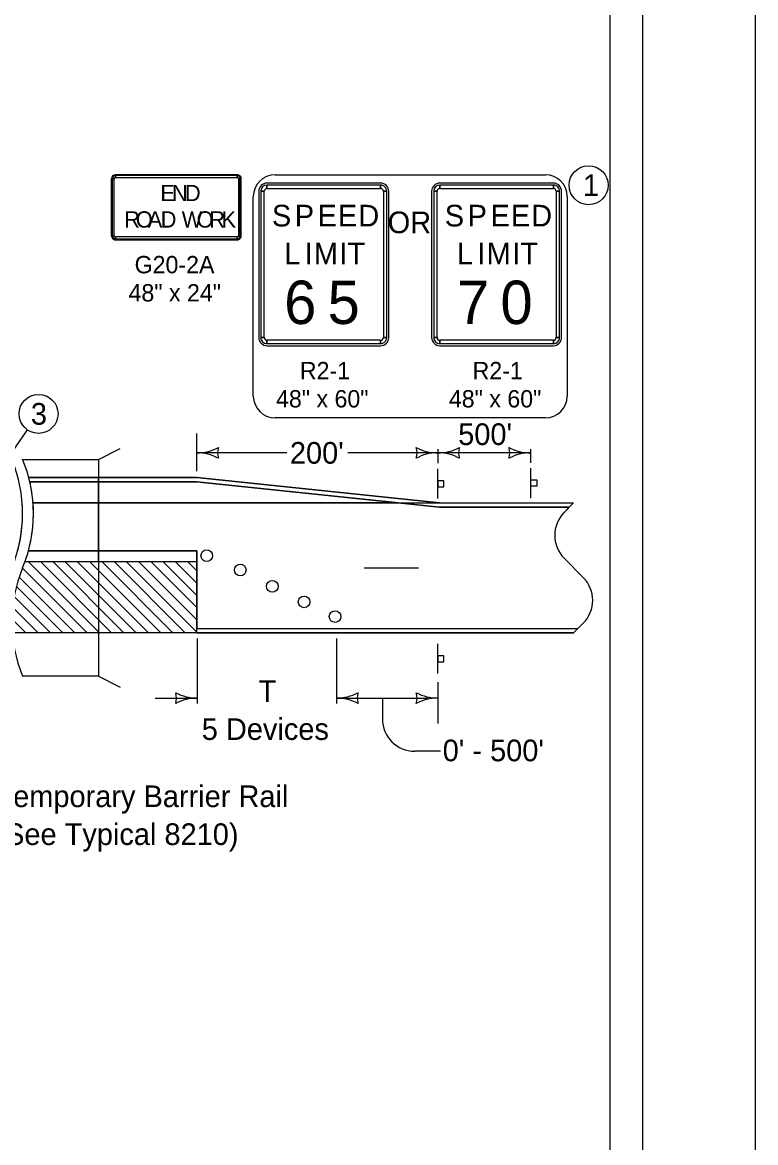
# Model space of a CAD drawing. Extents: x -2135039 to 114557, y -2139150 to -409929.
# Drawn here: x -2128772 to -2128095, y -2138203 to -2137170 of the extents above; entities that cross this region are included whole.
import ezdxf

# ---------------------------------------------------------------- set-up
doc = ezdxf.new("R2010")
doc.units = 0
for name, color, linetype in [('dsnDOTLogo', 7, 'Continuous'), ('dsnNonPlotable', 7, 'Continuous'), ('dsnStdDimension', 7, 'Continuous'), ('dsnStdLabel', 7, 'Continuous'), ('dsnStdLineWork', 7, 'Continuous'), ('dsnStdNote', 7, 'Continuous'), ('dsnStdShading', 7, 'Continuous'), ('Level 1', 7, 'Continuous'), ('StdDimension', 7, 'Continuous')]:
    doc.layers.add(name, color=color, linetype=linetype)

msp = doc.modelspace()

# ---------------------------------------------------------------- linework, layer by layer
at = {"layer": 'dsnDOTLogo'}
msp.add_lwpolyline([(-2131438.9, -2139150.4), (-2128095, -2139150.4), (-2128095, -2136566.4), (-2131438.9, -2136566.4)], close=True, dxfattribs=at)
at = {"layer": 'dsnNonPlotable'}
msp.add_line((-2128229.5, -2137085.9), (-2128229.5, -2138555.9), dxfattribs=at)
at = {"layer": 'dsnStdDimension'}
for p, q in [((-2128388.4, -2137563.5), (-2128388.4, -2137576.4)), ((-2128302.7, -2137566.8), (-2128388.4, -2137566.8)), ((-2128302.7, -2137563.5), (-2128302.7, -2137576.1))]:
    msp.add_line(p, q, dxfattribs=at)
at = {"layer": 'dsnStdLabel'}
for p, q in [((-2128573.6, -2137310.1), (-2128686.1, -2137310.1)), ((-2128686.1, -2137312.6), (-2128686.1, -2137311)), ((-2128573.6, -2137311), (-2128573.6, -2137312.6)), ((-2128689.9, -2137313.9), (-2128689.9, -2137366.4)), ((-2128689, -2137313.9), (-2128687.4, -2137313.9)), ((-2128572.4, -2137313.9), (-2128570.8, -2137313.9)), ((-2128569.9, -2137366.4), (-2128569.9, -2137313.9)), ((-2128441.2, -2137317.9), (-2128546.2, -2137317.9)), ((-2128546.2, -2137322.9), (-2128546.2, -2137319.7)), ((-2128441.2, -2137319.7), (-2128441.2, -2137322.9)), ((-2128281.6, -2137317.9), (-2128386.6, -2137317.9)), ((-2128386.6, -2137322.9), (-2128386.6, -2137319.7)), ((-2128281.6, -2137319.7), (-2128281.6, -2137322.9)), ((-2128553.7, -2137325.4), (-2128553.7, -2137460.4)), ((-2128551.8, -2137325.4), (-2128548.7, -2137325.4)), ((-2128438.7, -2137325.4), (-2128435.6, -2137325.4)), ((-2128433.7, -2137460.4), (-2128433.7, -2137325.4)), ((-2128394.1, -2137325.4), (-2128394.1, -2137460.4)), ((-2128392.2, -2137325.4), (-2128389.1, -2137325.4)), ((-2128279.1, -2137325.4), (-2128276, -2137325.4)), ((-2128274.1, -2137460.4), (-2128274.1, -2137325.4)), ((-2128687.4, -2137366.4), (-2128689, -2137366.4)), ((-2128686.1, -2137369.2), (-2128686.1, -2137367.6)), ((-2128686.1, -2137370.1), (-2128573.6, -2137370.1)), ((-2128573.6, -2137367.6), (-2128573.6, -2137369.2)), ((-2128570.8, -2137366.4), (-2128572.4, -2137366.4)), ((-2128548.7, -2137460.4), (-2128551.8, -2137460.4)), ((-2128546.2, -2137466), (-2128546.2, -2137462.9)), ((-2128441.2, -2137462.9), (-2128441.2, -2137466)), ((-2128435.6, -2137460.4), (-2128438.7, -2137460.4)), ((-2128389.1, -2137460.4), (-2128392.2, -2137460.4)), ((-2128386.6, -2137466), (-2128386.6, -2137462.9)), ((-2128281.6, -2137462.9), (-2128281.6, -2137466)), ((-2128276, -2137460.4), (-2128279.1, -2137460.4)), ((-2128546.2, -2137467.9), (-2128441.2, -2137467.9)), ((-2128386.6, -2137467.9), (-2128281.6, -2137467.9)), ((-2128388.4, -2137609), (-2128388.4, -2137581.5)), ((-2128302.7, -2137581), (-2128302.7, -2137608.5)), ((-2128611, -2137593.4), (-2128386.8, -2137616.9)), ((-2128386.8, -2137616.9), (-2128267, -2137616.9)), ((-2128753.3, -2137657.2), (-2128766.4, -2137657.2)), ((-2128701.8, -2137657.2), (-2128753.3, -2137657.2)), ((-2128611, -2137657.2), (-2128701.8, -2137657.2)), ((-2128701.8, -2137657.2), (-2128701.8, -2137667.2)), ((-2128701.8, -2137667.2), (-2128701.8, -2137657.2)), ((-2128611, -2137667.2), (-2128611, -2137657.2)), ((-2128769.5, -2137667.2), (-2128756.5, -2137667.2)), ((-2128766.6, -2137667.2), (-2128700.9, -2137732.9)), ((-2128756.5, -2137667.2), (-2128701.8, -2137667.2)), ((-2128755.3, -2137667.2), (-2128689.6, -2137732.9)), ((-2128744, -2137667.2), (-2128678.2, -2137732.9)), ((-2128732.7, -2137667.2), (-2128666.9, -2137732.9)), ((-2128721.3, -2137667.2), (-2128655.6, -2137732.9)), ((-2128710, -2137667.2), (-2128644.3, -2137732.9)), ((-2128701.8, -2137667.2), (-2128611, -2137667.2)), ((-2128698.7, -2137667.2), (-2128633, -2137732.9)), ((-2128687.4, -2137667.2), (-2128621.7, -2137732.9)), ((-2128676.1, -2137667.2), (-2128611, -2137732.3)), ((-2128664.8, -2137667.2), (-2128611, -2137720.9)), ((-2128653.5, -2137667.2), (-2128611, -2137709.6)), ((-2128642.2, -2137667.2), (-2128611, -2137698.3)), ((-2128630.8, -2137667.2), (-2128611, -2137687)), ((-2128619.5, -2137667.2), (-2128611, -2137675.7)), ((-2128611, -2137732.9), (-2128611, -2137667.2)), ((-2128775, -2137681.4), (-2128723.5, -2137732.9)), ((-2128771.9, -2137673.2), (-2128712.2, -2137732.9)), ((-2128777.6, -2137690.1), (-2128734.8, -2137732.9)), ((-2128779.6, -2137699.4), (-2128746.1, -2137732.9)), ((-2128781.1, -2137709.3), (-2128757.4, -2137732.9)), ((-2128781.7, -2137719.9), (-2128768.8, -2137732.9)), ((-2128700.9, -2137732.9), (-2128701.8, -2137732)), ((-2128701.8, -2137732), (-2128701.8, -2137732.9)), ((-2128701.8, -2137732.9), (-2128700.9, -2137732.9)), ((-2128388.4, -2137770.4), (-2128388.4, -2137742.9))]:
    msp.add_line(p, q, dxfattribs=at)
for points in [[(-2128573.6, -2137311), (-2128686.1, -2137311), (-2128686.1, -2137312.6), (-2128573.6, -2137312.6), (-2128573.6, -2137311)], [(-2128689, -2137313.9), (-2128689, -2137366.4), (-2128687.4, -2137366.4), (-2128687.4, -2137313.9), (-2128689, -2137313.9)], [(-2128570.8, -2137366.4), (-2128570.8, -2137313.9), (-2128572.4, -2137313.9), (-2128572.4, -2137366.4), (-2128570.8, -2137366.4)], [(-2128441.2, -2137319.7), (-2128546.2, -2137319.7), (-2128546.2, -2137322.9), (-2128441.2, -2137322.9), (-2128441.2, -2137319.7)], [(-2128281.6, -2137319.7), (-2128386.6, -2137319.7), (-2128386.6, -2137322.9), (-2128281.6, -2137322.9), (-2128281.6, -2137319.7)], [(-2128551.8, -2137325.4), (-2128551.8, -2137460.4), (-2128548.7, -2137460.4), (-2128548.7, -2137325.4), (-2128551.8, -2137325.4)], [(-2128435.6, -2137460.4), (-2128435.6, -2137325.4), (-2128438.7, -2137325.4), (-2128438.7, -2137460.4), (-2128435.6, -2137460.4)], [(-2128392.2, -2137325.4), (-2128392.2, -2137460.4), (-2128389.1, -2137460.4), (-2128389.1, -2137325.4), (-2128392.2, -2137325.4)], [(-2128276, -2137460.4), (-2128276, -2137325.4), (-2128279.1, -2137325.4), (-2128279.1, -2137460.4), (-2128276, -2137460.4)], [(-2128686.1, -2137369.2), (-2128573.6, -2137369.2), (-2128573.6, -2137367.6), (-2128686.1, -2137367.6), (-2128686.1, -2137369.2)], [(-2128546.2, -2137466), (-2128441.2, -2137466), (-2128441.2, -2137462.9), (-2128546.2, -2137462.9), (-2128546.2, -2137466)], [(-2128386.6, -2137466), (-2128281.6, -2137466), (-2128281.6, -2137462.9), (-2128386.6, -2137462.9), (-2128386.6, -2137466)], [(-2128388.3, -2137592.5), (-2128388.3, -2137598.2), (-2128382.7, -2137598.2), (-2128382.7, -2137592.5)], [(-2128302.6, -2137597.5), (-2128302.6, -2137591.8), (-2128297, -2137591.8), (-2128297, -2137597.5)], [(-2128388.3, -2137754), (-2128388.3, -2137759.6), (-2128382.7, -2137759.6), (-2128382.7, -2137754)]]:
    msp.add_lwpolyline(points, close=True, dxfattribs=at)
for points in [[(-2128538.7, -2137310.1), (-2128289.1, -2137310.1)], [(-2128558.8, -2137514.4), (-2128558.8, -2137330.2)], [(-2128269, -2137330.2), (-2128269, -2137514.4)], [(-2128289.1, -2137534.5), (-2128538.7, -2137534.5)]]:
    msp.add_lwpolyline(points, dxfattribs=at)
for centre in [(-2128601.8, -2137661.7), (-2128601.8, -2137661.7), (-2128570.8, -2137674.9), (-2128570.8, -2137674.9), (-2128541.2, -2137690), (-2128541.2, -2137690), (-2128511.9, -2137704.3), (-2128511.9, -2137704.3), (-2128483.3, -2137717.9), (-2128483.3, -2137717.9)]:
    msp.add_circle(centre, 5.37, dxfattribs=at)
for centre, radius, start, end in [((-2128686.1, -2137313.9), 3.75, 90.0002, 179.9998), ((-2128686.1, -2137313.9), 2.81, 90.0002, 179.9998), ((-2128573.6, -2137313.9), 3.75, 0, 90.0002), ((-2128573.6, -2137313.9), 2.81, 0, 90.0002), ((-2128538.7, -2137330.2), 20.1, 90, 180), ((-2128289.1, -2137330.2), 20.1, 0, 90), ((-2128686.1, -2137313.9), 1.25, 90.0002, 179.9998), ((-2128573.6, -2137313.9), 1.25, 0, 90.0002), ((-2128546.2, -2137325.4), 7.5, 90.0002, 179.9998), ((-2128546.2, -2137325.4), 5.62, 90.0002, 179.9998), ((-2128441.2, -2137325.4), 7.5, 0, 90.0002), ((-2128441.2, -2137325.4), 5.62, 0, 90.0002), ((-2128386.6, -2137325.4), 7.5, 90.0002, 179.9998), ((-2128386.6, -2137325.4), 5.62, 90.0002, 179.9998), ((-2128281.6, -2137325.4), 7.5, 0, 90.0002), ((-2128281.6, -2137325.4), 5.62, 0, 90.0002), ((-2128546.2, -2137325.4), 2.5, 90.0002, 179.9998), ((-2128441.2, -2137325.4), 2.5, 0, 90.0002), ((-2128386.6, -2137325.4), 2.5, 90.0002, 179.9998), ((-2128281.6, -2137325.4), 2.5, 0, 90.0002), ((-2128686.1, -2137366.4), 3.75, 179.9998, 270.0001), ((-2128686.1, -2137366.4), 2.81, 179.9998, 270.0001), ((-2128686.1, -2137366.4), 1.25, 179.9998, 270.0001), ((-2128573.6, -2137366.4), 3.75, 270.0001, 0.0003), ((-2128573.6, -2137366.4), 2.81, 270.0001, 0.0003), ((-2128573.6, -2137366.4), 1.25, 270.0001, 0.0003), ((-2128546.2, -2137460.4), 7.5, 179.9998, 270.0001), ((-2128546.2, -2137460.4), 5.62, 179.9998, 270.0001), ((-2128546.2, -2137460.4), 2.5, 179.9998, 270.0001), ((-2128441.2, -2137460.4), 7.5, 270.0001, 0.0003), ((-2128441.2, -2137460.4), 5.62, 270.0001, 0.0003), ((-2128441.2, -2137460.4), 2.5, 270.0001, 0.0003), ((-2128386.6, -2137460.4), 7.5, 179.9998, 270.0001), ((-2128386.6, -2137460.4), 5.62, 179.9998, 270.0001), ((-2128386.6, -2137460.4), 2.5, 179.9998, 270.0001), ((-2128281.6, -2137460.4), 7.5, 270.0001, 0.0003), ((-2128281.6, -2137460.4), 5.62, 270.0001, 0.0003), ((-2128281.6, -2137460.4), 2.5, 270.0001, 0.0003), ((-2128538.7, -2137514.4), 20.1, 180, 270), ((-2128289.1, -2137514.4), 20.1, 270, 0), ((-2128611, -2137524.3), 42.5, 270, 298.0725), ((-2128611, -2137609.3), 42.5, 61.9275, 90), ((-2128575.4, -2137566.8), 16.4, 162.2666, 197.7334), ((-2128424, -2137566.8), 16.4, 342.2667, 17.7334), ((-2128388.4, -2137524.3), 42.5, 241.9275, 270), ((-2128388.4, -2137609.3), 42.5, 90, 118.0725), ((-2128388.4, -2137524.3), 42.5, 270, 298.0725), ((-2128388.4, -2137609.3), 42.5, 61.9275, 90), ((-2128352.8, -2137566.8), 16.4, 162.2666, 197.7334), ((-2128338.4, -2137566.8), 16.4, 342.2667, 17.7334), ((-2128302.7, -2137524.3), 42.5, 241.9275, 270), ((-2128302.7, -2137609.3), 42.5, 90, 118.0725), ((-2128891.8, -2137622.9), 130, 340.0918, 344.7168)]:
    msp.add_arc(centre, radius, start, end, dxfattribs=at)
at = {"layer": 'dsnStdLineWork'}
for p, q in [((-2128701.8, -2137572.9), (-2128681.8, -2137562.9)), ((-2128771.8, -2137572.9), (-2128701.8, -2137572.9)), ((-2128765.2, -2137593.4), (-2128611, -2137593.4)), ((-2128611, -2137593.4), (-2128386.8, -2137616.9)), ((-2128762.2, -2137612.9), (-2128386.8, -2137612.9)), ((-2128263, -2137612.9), (-2128271.7, -2137621.7)), ((-2128611, -2137657.2), (-2128766.4, -2137657.2)), ((-2128611, -2137667.2), (-2128611, -2137657.2)), ((-2128769.5, -2137667.2), (-2128611, -2137667.2)), ((-2128271.7, -2137664.1), (-2128254.2, -2137681.7)), ((-2128254.2, -2137724.1), (-2128263, -2137732.9)), ((-2128701.8, -2137772.9), (-2128681.8, -2137782.9))]:
    msp.add_line(p, q, dxfattribs=at)
for points in [[(-2128701.8, -2137572.9), (-2128701.8, -2137772.9), (-2128771.8, -2137772.9)], [(-2128386.8, -2137616.9), (-2128267, -2137616.9)], [(-2128753.3, -2137657.2), (-2128766.4, -2137657.2)], [(-2128769.5, -2137667.2), (-2128756.5, -2137667.2)], [(-2128456.3, -2137672.9), (-2128406.3, -2137672.9)], [(-2128611, -2137728.9), (-2128259, -2137728.9)]]:
    msp.add_lwpolyline(points, dxfattribs=at)
for centre, radius, start, end in [((-2128901.8, -2137622.9), 130, 337.3801, 22.6199), ((-2128891.8, -2137622.9), 130, 337.3801, 22.6199), ((-2128250.5, -2137642.9), 30, 135, 225), ((-2128651.8, -2137722.9), 130, 157.3801, 202.6199), ((-2128275.4, -2137702.9), 30, 315, 45)]:
    msp.add_arc(centre, radius, start, end, dxfattribs=at)
at = {"layer": 'dsnStdNote'}
for centre in [(-2128249.2, -2137319.8), (-2128757.1, -2137530.8)]:
    msp.add_circle(centre, 18, dxfattribs=at)
at = {"layer": 'dsnStdShading'}
for p, q in [((-2128701.8, -2137589.4), (-2128766.2, -2137589.4)), ((-2128766.1, -2137589.4), (-2128611, -2137589.4)), ((-2128766.1, -2137589.4), (-2128753.1, -2137589.4)), ((-2128611, -2137589.4), (-2128701.8, -2137589.4)), ((-2128701.8, -2137589.4), (-2128701.8, -2137593.4)), ((-2128701.8, -2137593.4), (-2128701.8, -2137589.4)), ((-2128611, -2137589.4), (-2128386.8, -2137612.9)), ((-2128386.8, -2137612.9), (-2128611, -2137589.4)), ((-2128765.2, -2137593.4), (-2128752.1, -2137593.4)), ((-2128752.1, -2137593.4), (-2128701.8, -2137593.4)), ((-2128701.8, -2137593.4), (-2128611, -2137593.4)), ((-2128611, -2137593.4), (-2128701.8, -2137593.4)), ((-2128701.8, -2137593.4), (-2128701.8, -2137612.9)), ((-2128701.8, -2137612.9), (-2128701.8, -2137593.4)), ((-2128611, -2137593.4), (-2128425, -2137612.9)), ((-2128425, -2137612.9), (-2128611, -2137593.4)), ((-2128701.8, -2137612.9), (-2128762.2, -2137612.9)), ((-2128762.2, -2137612.9), (-2128701.8, -2137612.9)), ((-2128701.8, -2137612.9), (-2128468.6, -2137612.9)), ((-2128701.8, -2137657.2), (-2128701.8, -2137612.9)), ((-2128701.8, -2137612.9), (-2128701.8, -2137657.2)), ((-2128468.6, -2137612.9), (-2128263, -2137612.9)), ((-2128468.6, -2137612.9), (-2128425, -2137612.9)), ((-2128425, -2137612.9), (-2128386.8, -2137612.9)), ((-2128386.8, -2137616.9), (-2128425, -2137612.9)), ((-2128386.8, -2137616.9), (-2128424.9, -2137612.9)), ((-2128424.9, -2137612.9), (-2128386.8, -2137612.9)), ((-2128386.8, -2137612.9), (-2128263, -2137612.9)), ((-2128267, -2137616.9), (-2128386.8, -2137616.9)), ((-2128267, -2137616.9), (-2128386.8, -2137616.9)), ((-2128271.7, -2137621.7), (-2128267, -2137616.9)), ((-2128263, -2137612.9), (-2128267, -2137616.9)), ((-2128766.4, -2137657.2), (-2128753.3, -2137657.2)), ((-2128753.3, -2137657.2), (-2128701.8, -2137657.2)), ((-2128701.8, -2137657.2), (-2128611, -2137657.2)), ((-2128611, -2137657.2), (-2128611, -2137667.2)), ((-2128611, -2137667.2), (-2128611, -2137672.9)), ((-2128611, -2137672.9), (-2128611, -2137675.7)), ((-2128254.2, -2137681.7), (-2128271.7, -2137664.1)), ((-2128611, -2137675.7), (-2128611, -2137687)), ((-2128611, -2137687), (-2128611, -2137698.3)), ((-2128611, -2137720.9), (-2128611, -2137728.9)), ((-2128259, -2137728.9), (-2128254.2, -2137724.1)), ((-2128611, -2137732.9), (-2128781.4, -2137732.9)), ((-2128611, -2137728.9), (-2128259, -2137728.9)), ((-2128611, -2137728.9), (-2128259, -2137728.9)), ((-2128263, -2137732.9), (-2128611, -2137732.9)), ((-2128611, -2137732.9), (-2128263, -2137732.9)), ((-2128259, -2137728.9), (-2128263, -2137732.9))]:
    msp.add_line(p, q, dxfattribs=at)
for points in [[(-2128701.8, -2137593.4), (-2128752.1, -2137593.4), (-2128765.2, -2137593.4)], [(-2128425, -2137612.9), (-2128468.6, -2137612.9), (-2128701.8, -2137612.9)], [(-2128468.6, -2137612.9), (-2128468.6, -2137612.9)], [(-2128386.8, -2137612.9), (-2128386.8, -2137612.9)], [(-2128267, -2137616.9), (-2128267, -2137616.9)], [(-2128267, -2137616.9), (-2128267, -2137616.9)], [(-2128611, -2137698.3), (-2128611, -2137709.6), (-2128611, -2137720.9)], [(-2128611, -2137732.9), (-2128611, -2137732.3), (-2128611, -2137728.9)], [(-2128259, -2137728.9), (-2128259, -2137728.9)], [(-2128259, -2137728.9), (-2128259, -2137728.9)]]:
    msp.add_lwpolyline(points, dxfattribs=at)
for centre, radius, start, end in [((-2128891.8, -2137622.9), 130, 13.1174, 14.9346), ((-2128891.8, -2137622.9), 130, 4.4108, 13.1174), ((-2128901.8, -2137622.9), 130, 344.7177, 4.4117), ((-2128891.8, -2137622.9), 130, 344.7168, 4.4108), ((-2128250.5, -2137642.9), 30, 135, 225), ((-2128275.4, -2137702.9), 30, 315, 45)]:
    msp.add_arc(centre, radius, start, end, dxfattribs=at)
at = {"layer": 'Level 1'}
msp.add_lwpolyline([(-2131334.4, -2137035.9), (-2128199.5, -2137035.9), (-2128199.5, -2139045.9), (-2131334.4, -2139045.9)], close=True, dxfattribs=at)
at = {"layer": 'StdDimension'}
for p, q in [((-2128860.4, -2137679.9), (-2128767.3, -2137545.6)), ((-2128611, -2137583.7), (-2128611, -2137548.8)), ((-2128527.9, -2137566.8), (-2128611, -2137566.8)), ((-2128388.4, -2137566.8), (-2128471.6, -2137566.8)), ((-2128610.5, -2137738), (-2128610.5, -2137798.1)), ((-2128482, -2137738), (-2128482, -2137798.1)), ((-2128388.4, -2137778.4), (-2128388.4, -2137816.5)), ((-2128649.3, -2137793.1), (-2128610.4, -2137793.1)), ((-2128482, -2137793.1), (-2128397.3, -2137793.1)), ((-2128439.6, -2137793.1), (-2128439.6, -2137812.2)), ((-2128386, -2137842.2), (-2128409.6, -2137842.2))]:
    msp.add_line(p, q, dxfattribs=at)
for centre, radius, start, end in [((-2128646.1, -2137793.1), 16.4, 342.2667, 17.7334), ((-2128610.4, -2137750.6), 42.5, 241.9275, 270), ((-2128610.4, -2137835.6), 42.5, 90, 118.0725), ((-2128482, -2137750.6), 42.5, 270, 298.0725), ((-2128482, -2137835.6), 42.5, 61.9275, 90), ((-2128446.4, -2137793.1), 16.4, 162.2666, 197.7334), ((-2128424, -2137793.1), 16.4, 342.2667, 17.7334), ((-2128388.3, -2137750.6), 42.5, 241.9275, 270), ((-2128388.3, -2137835.6), 42.5, 90, 118.0725), ((-2128409.6, -2137812.2), 30, 180, 270)]:
    msp.add_arc(centre, radius, start, end, dxfattribs=at)

# ---------------------------------------------------------------- texts
at = {"layer": 'dsnStdDimension'}
for s, p in [("500'", (-2128369.6, -2137559.6)), ("200'", (-2128525, -2137576.8))]:
    msp.add_text(s, height=20, dxfattribs=at).set_placement(p)
at = {"layer": 'dsnStdLabel'}
for s, height, p in [('E', 15, (-2128644.6, -2137334.5)), ('N', 15, (-2128633.9, -2137334.5)), ('D', 15, (-2128621.9, -2137334.5)), ('S', 20, (-2128541.6, -2137357.9)), ('P', 20, (-2128520.5, -2137357.9)), ('E', 20, (-2128499.4, -2137357.9)), ('E', 20, (-2128480.6, -2137357.9)), ('D', 20, (-2128461.8, -2137357.9)), ('S', 20, (-2128382, -2137357.9)), ('P', 20, (-2128360.9, -2137357.9)), ('E', 20, (-2128339.8, -2137357.9)), ('E', 20, (-2128321, -2137357.9)), ('D', 20, (-2128302.2, -2137357.9)), ('R', 15, (-2128678, -2137358.9)), ('O', 15, (-2128667.3, -2137358.9)), ('A', 15, (-2128656.2, -2137358.9)), ('D', 15, (-2128644.3, -2137358.9)), ('W', 15, (-2128624.9, -2137358.9)), ('O', 15, (-2128611.1, -2137358.9)), ('R', 15, (-2128599.4, -2137358.9)), ('K', 15, (-2128588.1, -2137358.9)), ('OR', 20, (-2128434.7, -2137364.1)), ('L', 20, (-2128530.3, -2137392.9)), ('I', 20, (-2128511.5, -2137392.9)), ('M', 20, (-2128502.9, -2137392.9)), ('I', 20, (-2128479.3, -2137392.9)), ('T', 20, (-2128471.8, -2137392.9)), ('L', 20, (-2128370.7, -2137392.9)), ('I', 20, (-2128351.9, -2137392.9)), ('M', 20, (-2128343.3, -2137392.9)), ('I', 20, (-2128319.7, -2137392.9)), ('T', 20, (-2128312.2, -2137392.9)), ('G20-2A', 16, (-2128668.4, -2137401.1)), ('48" x 24"', 16, (-2128674, -2137427.1)), ('6', 40, (-2128530.3, -2137447.9)), ('5', 40, (-2128490.2, -2137447.9)), ('7', 40, (-2128370.7, -2137447.9)), ('0', 40, (-2128330.6, -2137447.9)), ('R2-1', 16, (-2128515.8, -2137498.9)), ('R2-1', 16, (-2128356.3, -2137498.9)), ('48" x 60"', 16, (-2128537.8, -2137524.9)), ('48" x 60"', 16, (-2128378.2, -2137524.9))]:
    msp.add_text(s, height=height, dxfattribs=at).set_placement(p)
at = {"layer": 'dsnStdNote'}
for s, p in [('1', (-2128254.4, -2137329.8)), ('3', (-2128764.2, -2137540.8))]:
    msp.add_text(s, height=20, dxfattribs=at).set_placement(p)
at = {"layer": 'StdDimension'}
for s, p in [('T', (-2128553.9, -2137796.7)), ('5 Devices', (-2128606.4, -2137831.7)), ("0' - 500'", (-2128383.9, -2137851.4)), ('Temporary Barrier Rail', (-2128796.9, -2137893.7)), ('(See Typical 8210)', (-2128796.9, -2137928.7))]:
    msp.add_text(s, height=20, dxfattribs=at).set_placement(p)

doc.saveas('drawing.dxf')
